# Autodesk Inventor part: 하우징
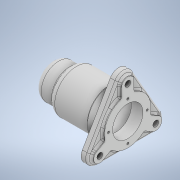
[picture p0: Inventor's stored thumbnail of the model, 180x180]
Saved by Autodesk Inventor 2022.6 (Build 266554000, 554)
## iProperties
Created: 2024-10
Part Number: 하우징
Material: 일반
Document SubType Name: Modeling
Designer: Class 003
Density: 1 g/cm^3
Appearance: 기본값
Author: Class 003
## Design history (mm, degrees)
sketch "스케치1"
  geometry: L1 (0, 0)-(117, 0); L2 (0, 0)-(0, 27); L3 (0, 27)-(28, 27); L4 (28, 27)-(28, 33.5); L5 (28, 33.5)-(91, 33.5); L6 (91, 33.5)-(91, 36.5); L7 (91, 36.5)-(103, 36.5); L8 (103, 36.5)-(103, 0); 1 further point
  constraints: 16 end point, 6 perpendicular, 1 horizontal, 1 midpoint, 1 point on line, 1 vertical
  dimensions: "d1" = 27 distance of L1.start L2.end; "d2" = 28 distance of L2.end L3.end; "d4" = 67 diameter of L5 L1; "d5" = 73 diameter of point (97, 36.5) L1; "d6" = 63 distance of L4.end L5.end; "d7" = 12 distance of L6.end L7.end
revolve "회전1" sketch "스케치1" stored, may be unused: angle "d8" = 360 deg
fillet "모깎기1" dims "d9" = 10
fillet "모깎기2" dims "d10" = 3
sketch "스케치2"
  geometry: L1 (0, 80)-(69.282, -40); L2 (69.282, -40)-(-69.282, -40); L3 (-69.282, -40)-(0, 80); 3 further points
  constraints: 6 end point, 1 coincident, 1 midpoint, 7 other
  dimensions: "d11" = 120 distance of point (0, -40) L1.start
extrude "돌출1" join sketch "스케치2" distance "d12" = 10; taper "d13" = 0 deg
fillet "모깎기3" dims "d14" = 15
sketch "스케치3"
  geometry: L1 (0, -50)-(0, 50); L2 (-9.5, 50)-(-9.5, 34.724); L3 (9.5, 34.724)-(9.5, 50); L4 (-38.551, -33.227)-(-25.322, -25.589); L5 (-34.822, -9.135)-(-48.051, -16.773); L6 (48.051, -16.773)-(34.822, -9.135); L7 (25.322, -25.589)-(38.551, -33.227); C1 r 17 at (0, 0) reference; A1 r 15 centre (0, 50) between (12.99, 57.5) and (-12.99, 57.5) reference; A2 r 15 centre (-43.301, -25) between (-56.292, -17.5) and (-43.301, -40) reference; A3 r 15 centre (43.301, -25) between (43.301, -40) and (56.292, -17.5) reference; A4 r 9.5 centre (0, 50) between (9.5, 50) and (-9.5, 50); A5 r 9.5 centre (-43.301, -25) between (-48.051, -16.773) and (-38.551, -33.227); A6 r 9.5 centre (43.301, -25) between (38.551, -33.227) and (48.051, -16.773); A7 r 36 centre (0, 0) between (-9.5, 34.724) and (-34.822, -9.135); A8 r 36 centre (0, 0) between (-25.322, -25.589) and (25.322, -25.589); A9 r 36 centre (0, 0) between (34.822, -9.135) and (9.5, 34.724); 1 further point
  constraints: 16 end point, 12 point on circle, 6 centre point, 2 tangent, 1 coincident, 1 midpoint, 1 parallel, 1 vertical, 25 other
  dimensions: "d16" = 19 diameter of A4; "d19" = 360 deg dimension on C1.centre L2.start (derived)
extrude "돌출2" join sketch "스케치3" distance "d21" = 4; taper "d22" = 0 deg
sketch "스케치4"
  geometry: A1 r 9.5 centre (0, 50) between (9.5, 50) and (-9.5, 50) reference; A2 r 9.5 centre (-43.301, -25) between (-48.051, -16.773) and (-38.551, -33.227) reference; A3 r 9.5 centre (43.301, -25) between (38.551, -33.227) and (48.051, -16.773) reference; 1 further point
hole "구멍1" sketch "스케치4" at (0, 50), (43.301, -25), (-43.301, -25) diameter "d24" = 9; stored, may be unused: countersink angle "d28" = 90 deg, drill point angle "d30" = 118 deg; dims "d25" = 6, "d26" = 4, "d27" = 2, "d29" = 8
node "작업 평면1"
sketch "스케치5"
  geometry: L1 (0, 0)-(123.66, 0); L2 (10, 27)-(10, -27) reference; L3 (10, 0)-(15, 0); L4 (15, 0)-(15, 13.981); L5 (15, 13.981)-(10, 13.981); L6 (10, 13.981)-(10, 0); L7 (15, 0)-(19, 0); L8 (19, 0)-(19, 17.5); L9 (19, 17.5)-(15, 17.5); L10 (15, 17.5)-(15, 0); L11 (19, 0)-(37, 0); L12 (37, 0)-(37, 20.998); L13 (37, 20.998)-(19, 20.998); L14 (19, 20.998)-(19, 0); L15 (37, 0)-(51, 0); L16 (51, 0)-(51, 23.5); L17 (51, 23.5)-(37, 23.5); L18 (37, 23.5)-(37, 0); L19 (51, 0)-(99, 0); L20 (99, 0)-(99, 29.62); L21 (99, 29.62)-(51, 29.62); L22 (51, 29.62)-(51, 0); L23 (99, 0)-(117, 0); L24 (117, 0)-(117, 23.5); L25 (117, 23.5)-(99, 23.5); L26 (99, 23.5)-(99, 0); 6 further points
  constraints: 50 end point, 12 parallel, 7 horizontal, 6 perpendicular, 1 midpoint, 1 point on line
  dimensions: "d32" = 107 distance of L3.start L23.end; "d33" = 48 distance of L20.end L21.end; "d34" = 5 distance of L4.end L5.end; "d35" = 17.5 distance between parallel lines of L1 L9; "d36" = 18 distance of L12.end L13.end; "d37" = 23.5 distance between parallel lines of L15 L17; "d38" = 14 distance of L16.end L17.end; "d39" = 4 distance of L8.end L9.end
revolve "회전2" sketch "스케치5" stored, may be unused: angle "d40" = 360 deg
fillet "모깎기5" dims "d41" = 3
chamfer "모따기1" distance "d42" = 1; stored, may be unused: second distance "d43" = 2, angle "d44" = 45 deg
fillet "모깎기6" dims "d45" = 3
fillet "모깎기7" dims "d46" = 1
sketch "스케치6" dims "d47" = 60
  geometry: 3 further points
  constraints: 2 vertical alignment, 1 coincident, 2 other
hole "구멍2" sketch "스케치6" at (0, 30) diameter "d48" = 3.242; stored, may be unused: countersink angle "d52" = 90 deg, drill point angle "d54" = 118 deg; dims "d49" = 10, "d50" = 4, "d51" = 2, "d53" = 12
fillet "모깎기8" dims "d58" = 3
fillet "모깎기9" dims "d59" = 3
node "솔리드1"
pattern_circular "원형 패턴1" dims angle "d56" = 360 deg
feature "A9D066F2-1C7D-4E18-AEED-F7BC21143FA4" dims "d48" = 3.242, "d49" = 10, "d50" = 4, "d51" = 2, "d52" = 90 deg, "d53" = 12, "d54" = 118 deg
other parameters: "d15" = 72, "d31" = 0
